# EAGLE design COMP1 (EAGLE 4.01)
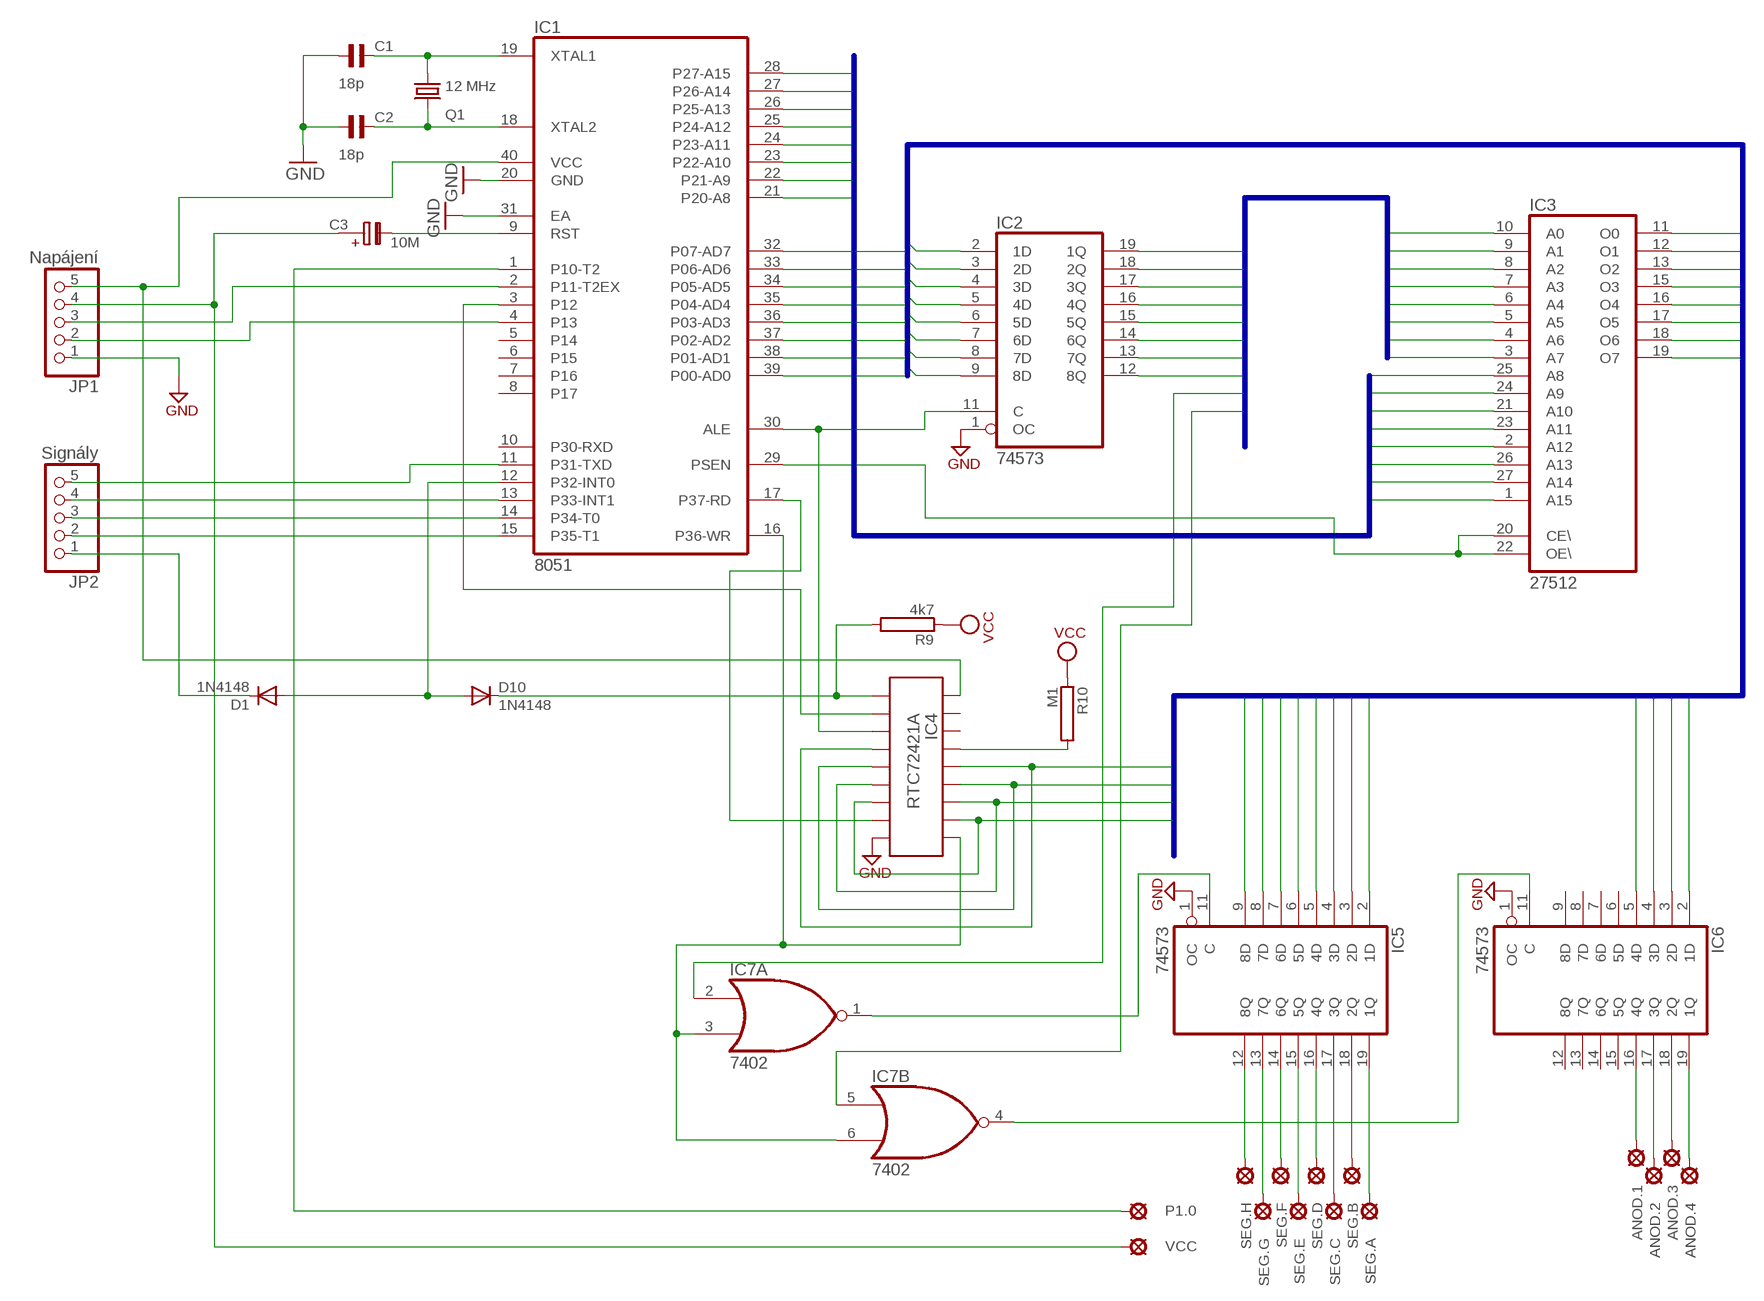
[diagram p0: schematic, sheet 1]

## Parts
ANOD.1  LSP10  [LSP10]
ANOD.2  LSP10  [LSP10]
ANOD.3  LSP10  [LSP10]
ANOD.4  LSP10  [LSP10]
C1  18p  C2,5  [C2,5-4]
C2  18p  C2,5  [C2,5-4]
C3  10M  TT2D4  [TT2D4]
D1  1N4148  [DO35-10]
D10  1N4148  [DO35-10]
IC1  8051  [DIL40]
IC2  74573  [DIL20]
IC3  27512  [DIL28]
IC4  RTC72421A  [DIL-18]
IC5  74573  [DIL20]
IC6  74573  [DIL20]
IC7  7402  [DIL14]
JP1  Napájení  PINHD-1X5  [1X05]
JP2  Signály  PINHD-1X5  [1X05]
P1.0  LSP10  [LSP10]
Q1  12 MHz  HC49U-V  [HC49U-V]
R9  4k7  0204/5  [0204/5]
R10  M1  0204/5  [0204/5]
SEG.A  LSP10  [LSP10]
SEG.B  LSP10  [LSP10]
SEG.C  LSP10  [LSP10]
SEG.D  LSP10  [LSP10]
SEG.E  LSP10  [LSP10]
SEG.F  LSP10  [LSP10]
SEG.G  LSP10  [LSP10]
SEG.H  LSP10  [LSP10]
VCC  LSP10  [LSP10]

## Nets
+5V/1: IC1.40(VCC) IC4.18 JP1.5
A0: IC2.19(1Q) IC3.10(A0)
A1: IC2.18(2Q) IC3.9(A1)
A2: IC2.17(3Q) IC3.8(A2)
A3: IC2.16(4Q) IC3.7(A3)
A4: IC2.15(5Q) IC3.6(A4) IC7.5(B:I0)
A5: IC2.14(6Q) IC3.5(A5) IC7.2(A:I0)
A6: IC2.13(7Q) IC3.4(A6)
A7: IC2.12(8Q) IC3.3(A7)
A8: IC1.21(P20-A8) IC3.25(A8)
A9: IC1.22(P21-A9) IC3.24(A9)
A10: IC1.23(P22-A10) IC3.21(A10)
A11: IC1.24(P23-A11) IC3.23(A11)
A12: IC1.25(P24-A12) IC3.2(A12)
A13: IC1.26(P25-A13) IC3.26(A13)
A14: IC1.27(P26-A14) IC3.27(A14)
A15: IC1.28(P27-A15) IC3.1(A15)
DB0: IC1.39(P00-AD0) IC2.2(1D) IC3.11(O0) IC4.4 IC4.14 IC5.2(1D) IC6.2(1D)
DB1: IC1.38(P01-AD1) IC2.3(2D) IC3.12(O1) IC4.5 IC4.13 IC5.3(2D) IC6.3(2D)
DB2: IC1.37(P02-AD2) IC2.4(3D) IC3.13(O2) IC4.6 IC4.12 IC5.4(3D) IC6.4(3D)
DB3: IC1.36(P03-AD3) IC2.5(4D) IC3.15(O3) IC4.7 IC4.11 IC5.5(4D) IC6.5(4D)
DB4: IC1.35(P04-AD4) IC2.6(5D) IC3.16(O4) IC5.6(5D)
DB5: IC1.34(P05-AD5) IC2.7(6D) IC3.17(O5) IC5.7(6D)
DB6: IC1.33(P06-AD6) IC2.8(7D) IC3.18(O6) IC5.8(7D)
DB7: IC1.32(P07-AD7) IC2.9(8D) IC3.19(O7) IC5.9(8D)
GND: C1.1 C2.1 IC1.20(GND) IC1.31(EA) IC2.1(OC) IC4.9 IC5.1(OC) IC6.1(OC) JP1.1
N$1: C2.2 IC1.18(XTAL2) Q1.2
N$2: C1.2 IC1.19(XTAL1) Q1.1
N$3: IC5.11(C) IC7.1(A:O)
N$4: IC6.11(C) IC7.4(B:O)
N$5: IC5.12(8Q) SEG.H.MP
N$6: IC5.13(7Q) SEG.G.MP
N$7: IC5.14(6Q) SEG.F.MP
N$8: IC5.15(5Q) SEG.E.MP
N$9: IC5.16(4Q) SEG.D.MP
N$10: IC1.11(P31-TXD) JP2.5
N$11: IC5.17(3Q) SEG.C.MP
N$13: IC5.18(2Q) SEG.B.MP
N$14: IC1.1(P10-T2) P1.0.MP
N$15: IC5.19(1Q) SEG.A.MP
N$16: ANOD.4.MP IC6.19(1Q)
N$17: D1.A D10.A IC1.12(P32-INT0)
N$18: ANOD.3.MP IC6.18(2Q)
N$19: ANOD.2.MP IC6.17(3Q)
N$21: IC1.14(P34-T0) JP2.3
N$22: ANOD.1.MP IC6.16(4Q)
N$23: C3.- IC1.9(RST)
N$24: IC1.2(P11-T2EX) JP1.3
N$25: IC1.4(P13) JP1.2
N$26: IC1.13(P33-INT1) JP2.4
N$27: IC1.30(ALE) IC2.11(C) IC4.3
N$28: IC1.29(PSEN) IC3.20(CE\) IC3.22(OE\)
N$29: D1.K JP2.1
N$32: IC1.15(P35-T1) JP2.2
N$33: D10.K IC4.1 R9.2
N$34: IC1.3(P12) IC4.2
N$35: IC4.15 R10.2
N$37: IC1.17(P37-RD) IC4.8
N$38: IC1.16(P36-WR) IC4.10 IC7.3(A:I1) IC7.6(B:I1)
VCC: C3.+ JP1.4 R9.1 R10.1 VCC.MP
Unconnected: IC1.5(P14) IC1.6(P15) IC1.7(P16) IC1.8(P17) IC1.10(P30-RXD) IC4.16 IC4.17 IC6.6(5D) IC6.7(6D) IC6.8(7D) IC6.9(8D) IC6.12(8Q) IC6.13(7Q) IC6.14(6Q) IC6.15(5Q) IC7.8(C:I0) IC7.9(C:I1) IC7.10(C:O) IC7.11(D:I0) IC7.12(D:I1) IC7.13(D:O)

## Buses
A[8..15]
DB[0..7]
A[0..7]

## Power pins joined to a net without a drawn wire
GND: IC2.10(GND) IC3.14(GND) IC5.10(GND) IC6.10(GND) IC7.7(P:GND)
VCC: IC2.20(VCC) IC3.28(VCC) IC5.20(VCC) IC6.20(VCC) IC7.14(P:VCC)

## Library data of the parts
ANOD.1-ANOD.4 P1.0 SEG.A SEG.B SEG.C SEG.D SEG.E SEG.F SEG.G SEG.H VCC = SOLPAD:LSP10
C1 C2 = cap:C2,5
C3 = CAP-TANT:TT2D4
D1 D10 = DIODE:1N4148
IC1 = INTEL:8051
IC2 IC5 IC6 = 74XX:74573
IC3 = MEMORY:27512
IC4 = GM397:RTC72421A
IC7 = 74XX:7402
JP1 JP2 = PINHEADb:PINHD-1X5
Q1 = QUARTZ:HC49U-V
R9 R10 = R:0204/5

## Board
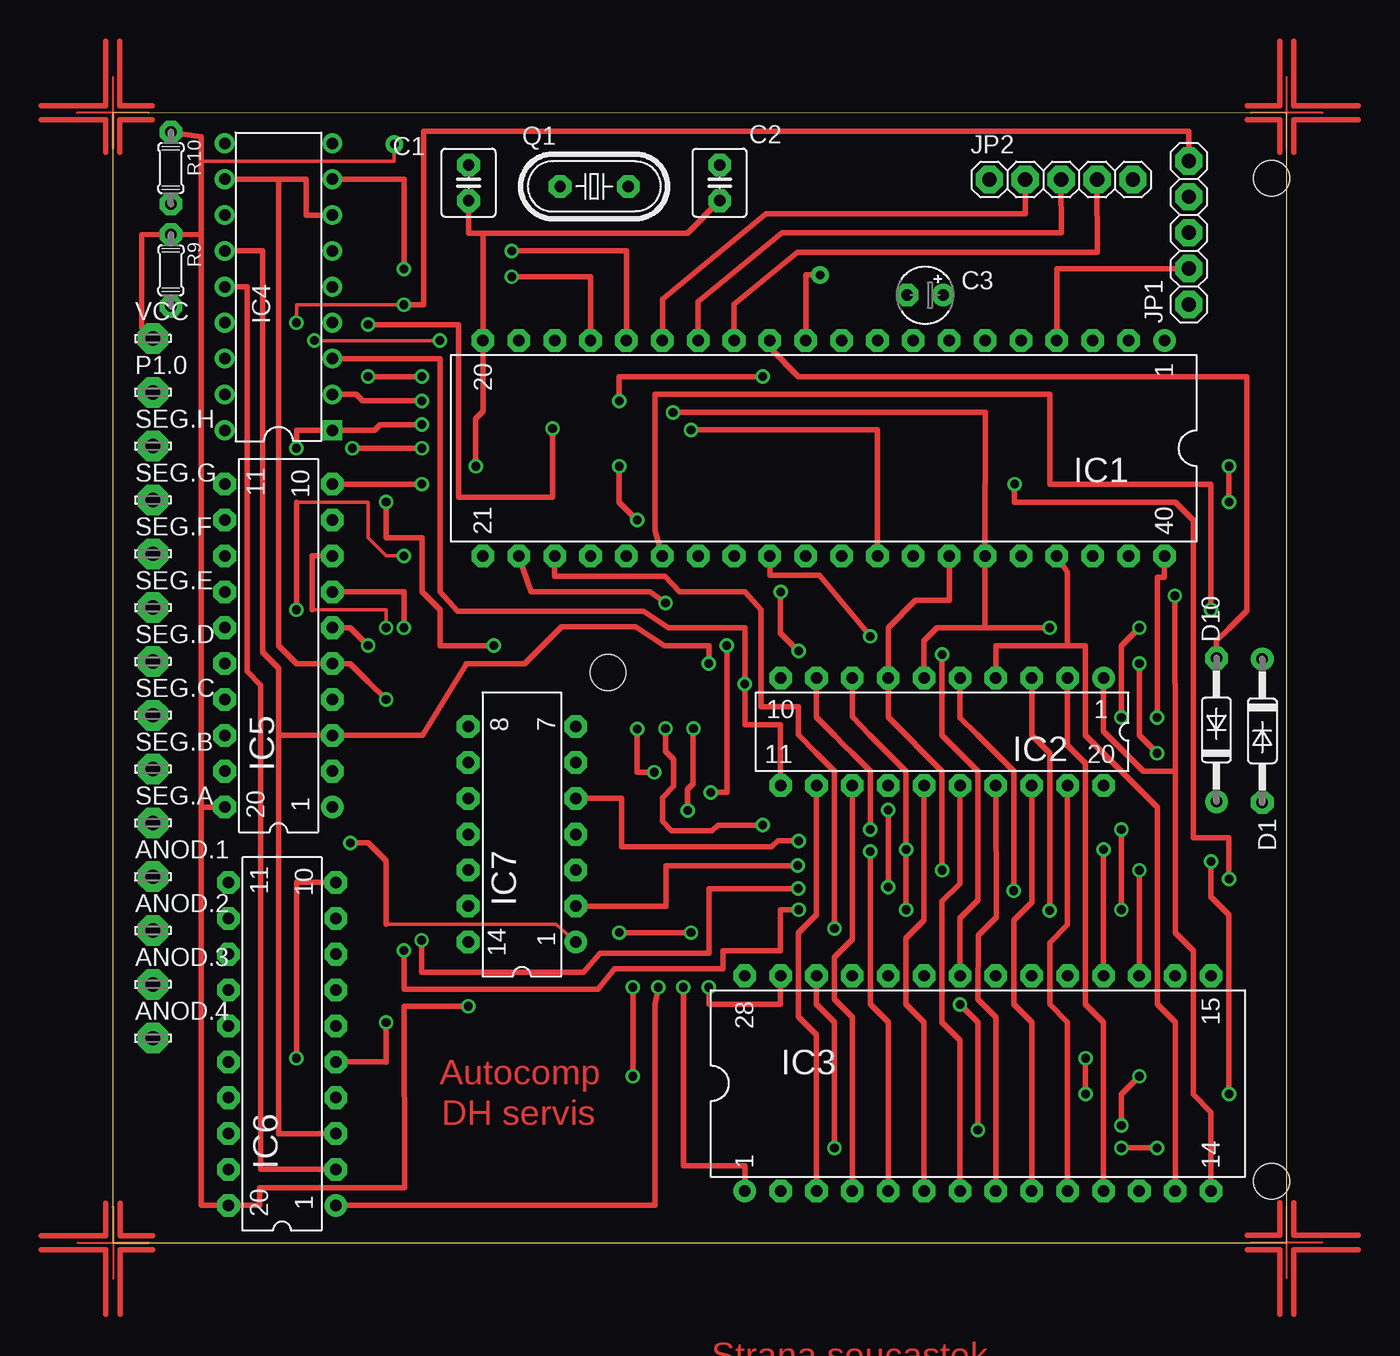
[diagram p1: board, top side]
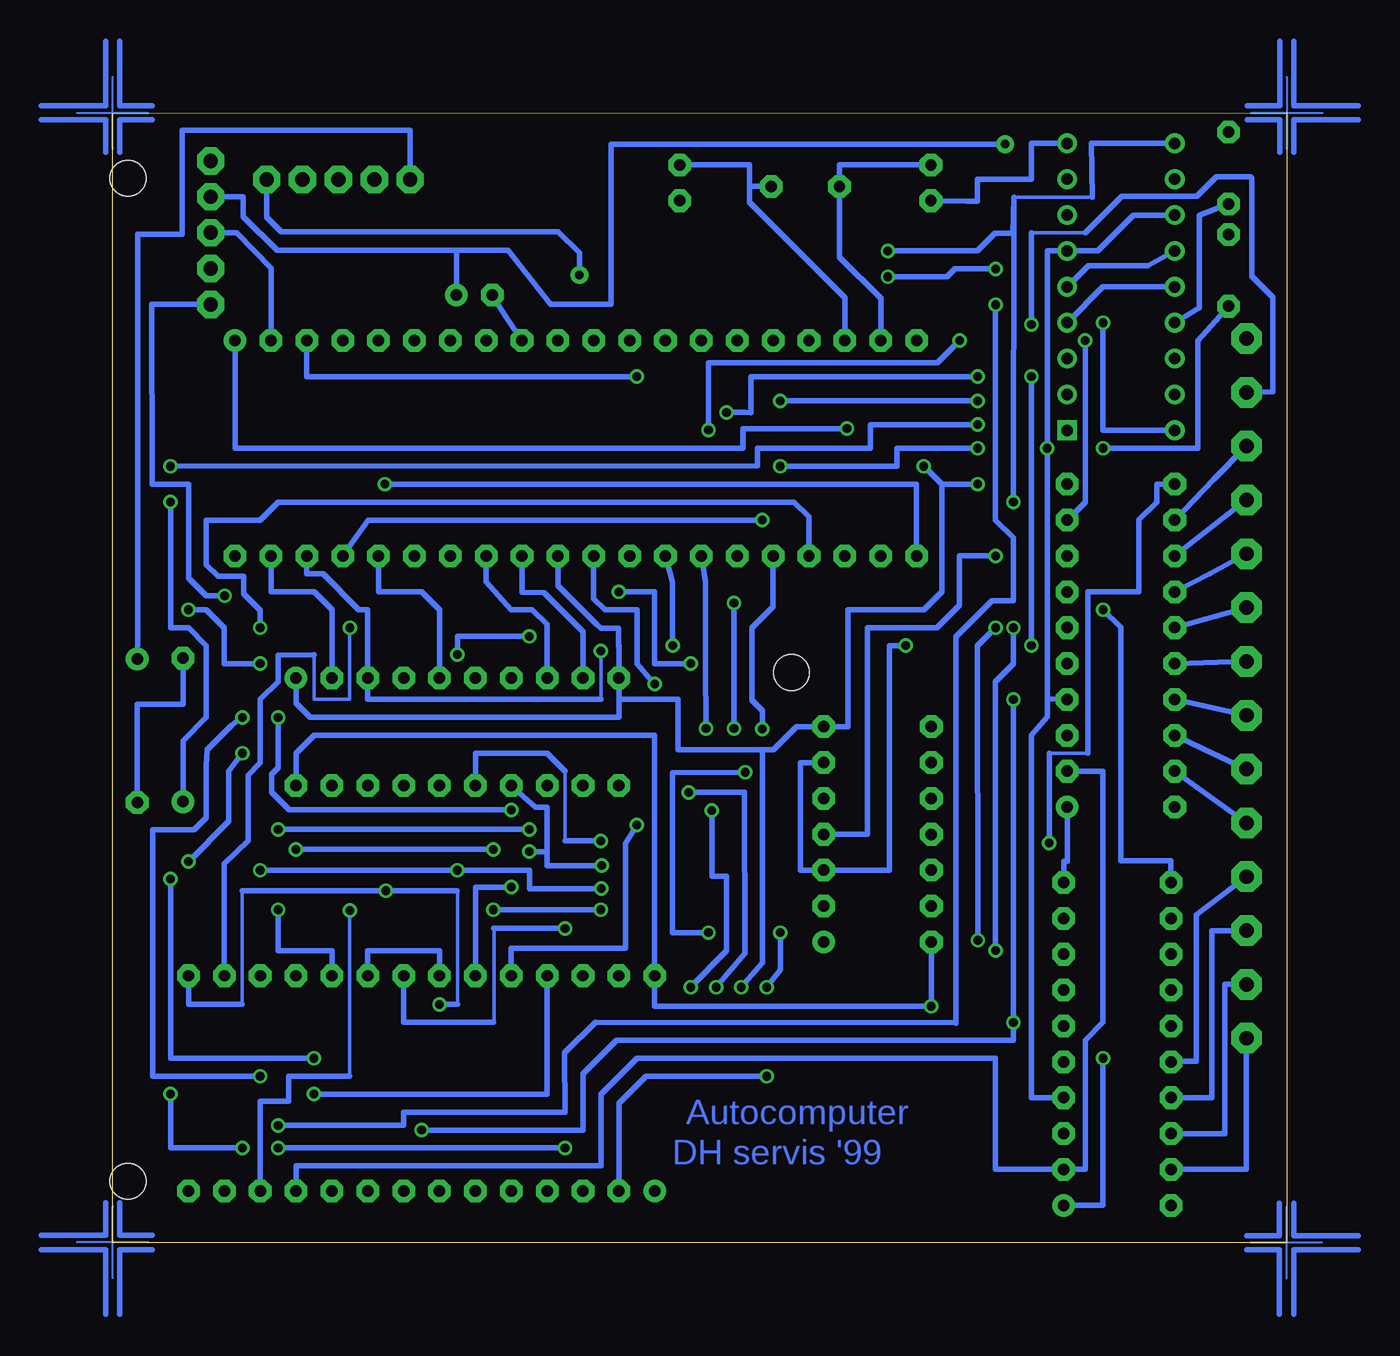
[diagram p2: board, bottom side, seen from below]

Size 83.13 x 80 mm. Coordinates in mm from the lower left corner, seen from the top.
Outline: 0,0.02 83.13,0 83.13,79.98 0,80 0,0.02
Copper layers used: Top, Bottom
Holes 2.54 mm at 35.05,40.38 82.05,4.38 82.05,75.38

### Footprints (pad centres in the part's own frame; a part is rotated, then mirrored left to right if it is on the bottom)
LSP10 = drill 1.016 pad 2.159 octagon: MP 0,0
C2,5-4 = drill 0.813 pad 1.6 octagon: 1 -1.27,0; 2 1.27,0
TT2D4 = drill 0.813 pad 1.6 round: + 1.27,0 | drill 0.813 pad 1.6 octagon: - -1.27,0
DO35-10 = drill 0.813 pad 1.6 octagon: A 5.08,0 | drill 0.813 pad 1.6 round: K -5.08,0
DIL40 = drill 0.813 pad 1.6 round: 1 -24.13,-7.62 | drill 0.813 pad 1.6 octagon: 2 -21.59,-7.62; 3 -19.05,-7.62; 4 -16.51,-7.62; 5 -13.97,-7.62; 6 -11.43,-7.62; 7 -8.89,-7.62; 8 -6.35,-7.62; 9 -3.81,-7.62; 10 -1.27,-7.62; 11 1.27,-7.62; 12 3.81,-7.62; 13 6.35,-7.62; 14 8.89,-7.62; 15 11.43,-7.62; 16 13.97,-7.62; 17 16.51,-7.62; 18 19.05,-7.62; 19 21.59,-7.62; 20 24.13,-7.62; 21 24.13,7.62; 22 21.59,7.62; 23 19.05,7.62; 24 16.51,7.62; 25 13.97,7.62; 26 11.43,7.62; 27 8.89,7.62; 28 6.35,7.62; 29 3.81,7.62; 30 1.27,7.62; 31 -1.27,7.62; 32 -3.81,7.62; 33 -6.35,7.62; 34 -8.89,7.62; 35 -11.43,7.62; 36 -13.97,7.62; 37 -16.51,7.62; 38 -19.05,7.62; 39 -21.59,7.62; 40 -24.13,7.62
DIL20 = drill 0.813 pad 1.6 round: 1 -11.43,-3.81 | drill 0.813 pad 1.6 octagon: 2 -8.89,-3.81; 3 -6.35,-3.81; 4 -3.81,-3.81; 5 -1.27,-3.81; 6 1.27,-3.81; 7 3.81,-3.81; 8 6.35,-3.81; 9 8.89,-3.81; 10 11.43,-3.81; 11 11.43,3.81; 12 8.89,3.81; 13 6.35,3.81; 14 3.81,3.81; 15 1.27,3.81; 16 -1.27,3.81; 17 -3.81,3.81; 18 -6.35,3.81; 19 -8.89,3.81; 20 -11.43,3.81
DIL28 = drill 0.813 pad 1.6 round: 1 -16.51,-7.62 | drill 0.813 pad 1.6 octagon: 2 -13.97,-7.62; 3 -11.43,-7.62; 4 -8.89,-7.62; 5 -6.35,-7.62; 6 -3.81,-7.62; 7 -1.27,-7.62; 8 1.27,-7.62; 9 3.81,-7.62; 10 6.35,-7.62; 11 8.89,-7.62; 12 11.43,-7.62; 13 13.97,-7.62; 14 16.51,-7.62; 15 16.51,7.62; 16 13.97,7.62; 17 11.43,7.62; 18 8.89,7.62; 19 6.35,7.62; 20 3.81,7.62; 21 1.27,7.62; 22 -1.27,7.62; 23 -3.81,7.62; 24 -6.35,7.62; 25 -8.89,7.62; 26 -11.43,7.62; 27 -13.97,7.62; 28 -16.51,7.62
DIL-18 = drill 0.813 pad 1.397 square: 1 -10.16,-3.81 | drill 0.813 pad 1.397 round: 2 -7.62,-3.81; 3 -5.08,-3.81; 4 -2.54,-3.81; 5 0,-3.81; 6 2.54,-3.81; 7 5.08,-3.81; 8 7.62,-3.81; 9 10.16,-3.81; 10 10.16,3.81; 11 7.62,3.81; 12 5.08,3.81; 13 2.54,3.81; 14 0,3.81; 15 -2.54,3.81; 16 -5.08,3.81; 17 -7.62,3.81; 18 -10.16,3.81
DIL14 = drill 0.813 pad 1.6 round: 1 -7.62,-3.81 | drill 0.813 pad 1.6 octagon: 2 -5.08,-3.81; 3 -2.54,-3.81; 4 0,-3.81; 5 2.54,-3.81; 6 5.08,-3.81; 7 7.62,-3.81; 8 7.62,3.81; 9 5.08,3.81; 10 2.54,3.81; 11 0,3.81; 12 -2.54,3.81; 13 -5.08,3.81; 14 -7.62,3.81
1X05 = drill 1.016 pad 1.93 octagon: 1 -5.08,0; 2 -2.54,0; 3 0,0; 4 2.54,0; 5 5.08,0
HC49U-V = drill 0.813 pad 1.6 octagon: 1 -2.413,0; 2 2.413,0
0204/5 = drill 0.813 pad 1.6 octagon: 1 -2.54,0; 2 2.54,0

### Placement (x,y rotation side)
ANOD.1  2.83,25.93 0 top
ANOD.2  2.83,22.12 0 top
ANOD.3  2.83,18.31 0 top
ANOD.4  2.83,14.5 0 top
C1  25.18,75.05 90 top
C2  42.96,75.05 90 top
C3  57.52,67.1 0 top
D1  81.39,36.25 270 top
D10  78.14,36.32 90 top
E$1  [ROH]  -0.01,80.01 270 top
E$2  [ROH]  0.01,0.02 0 top
E$3  [ROH]  83.12,80.01 180 top
E$4  [ROH]  83.12,0.05 90 top
IC1  50.33,56.26 180 top
IC2  58.71,36.19 180 top
IC3  61.25,11.3 0 top
IC4  11.72,67.69 90 top
IC5  11.72,42.29 90 top
IC6  11.98,14.09 90 top
IC7  28.96,28.93 90 top
JP1  76.19,71.52 90 top
JP2  67.14,75.28 0 top
P1.0  2.83,60.22 0 top
Q1  34.07,74.8 0 top
R9  4.1,68.85 270 top
R10  4.1,76.09 270 top
SEG.A  2.83,29.74 0 top
SEG.B  2.83,33.55 0 top
SEG.C  2.83,37.36 0 top
SEG.D  2.83,41.17 0 top
SEG.E  2.83,44.98 0 top
SEG.F  2.83,48.79 0 top
SEG.G  2.83,52.6 0 top
SEG.H  2.83,56.41 0 top
VCC  2.83,64.03 0 top

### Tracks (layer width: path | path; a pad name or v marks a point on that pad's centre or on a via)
+5V/1  (via drill 0.61 pad 1.02)
  Top 0.254: v12.99,65.15 12.99,66.42 v20.61,66.42
  Top 0.406: v20.61,66.42 21.98,66.42 21.98,78.68 76.19,78.68 JP1.5 | v73.95,37.21 73.95,47.11 74.46,47.11 IC1.40 | v72.68,11.81 71.41,10.54 v71.41,8.33
  Bottom 0.406: IC4.18 12.99,57.53 v12.99,65.15 | v72.68,11.81 80.3,11.81 80.3,29.26 77.36,29.26 76.49,30.12 76.49,33.75 76.44,34.92 74.71,36.65 v73.95,37.21 | v71.41,8.33 62.52,8.35 62.52,9.27 51.09,9.27 51.12,13.46 48.93,15.62 23.46,15.59 23.41,15.62 | v20.61,66.42 20.61,51.18 19.34,49.91 19.34,45.46 20.87,45.46 23.41,42.92 23.41,15.62 | 23.41,15.62 23.41,15.56
A0
  Top 0.406: IC3.10 67.6,15.62 66.33,16.89 66.33,21.05 66.33,21.26 67.6,22.53 IC2.19
A1
  Top 0.406: IC3.9 65.06,15.62 63.79,16.89 63.79,22.58 63.79,22.86 65.06,24.12 IC2.18
A2
  Top 0.406: IC3.8 62.52,15.97 61.25,17.24 61.3,21.79 62.57,23.06 IC2.17
A3
  Top 0.406: IC3.7 59.98,14.35 58.71,15.62 58.71,24.18 59.98,25.45 IC2.16
A4  (via drill 0.61 pad 1.02)
  Top 0.406: IC3.6 57.44,15.62 56.17,16.89 56.17,20.95 56.17,21.56 57.44,22.83 IC2.15 | IC7.5 36.03,31.47 36.03,28.04 46.65,28.04 47.08,28.47 v48.55,28.47
  Bottom 0.254: 51.09,33.4 51.09,28.47
  Bottom 0.406: 51.09,28.47 v48.55,28.47 | 51.09,33.4 52.36,34.67 57.44,34.67 IC2.15 57.44,32.13
A5  (via drill 0.61 pad 1.02)
  Top 0.406: v53.63,27.71 53.63,16.89 54.9,15.62 IC3.5 | v48.5,26.72 39.15,26.69 39.15,23.85 | IC7.2 39.15,23.85 | 39.15,23.85
  Bottom 0.406: 52.36,27.71 v53.63,27.71 | 52.36,27.71 52.36,30.86 53.17,30.86 IC2.14 | v48.5,26.72 52.36,26.72 52.36,27.71
A6
  Top 0.406: IC3.4 52.36,15.97 51.09,17.24 51.09,20.24 52.36,21.51 IC2.13
A7
  Top 0.406: IC3.3 49.82,14.75 48.55,16.02 48.55,21.97 49.82,23.24 IC2.12
A8  (via drill 0.61 pad 1.02)
  Top 0.406: v68.87,10.54 v68.87,13.08 | v79.03,25.78 79.03,28.67 76.49,28.67 76.49,51.18 75.22,52.45 63.84,52.45 v63.84,53.72
  Bottom 0.406: 53.76,10.54 v68.87,10.54 | v68.87,13.08 79.03,13.08 v79.03,25.78 | v63.84,53.72 26.2,53.72 IC1.21 | 53.76,10.54 53.63,10.54 | IC3.25 52.36,10.54 53.76,10.54
A9  (via drill 0.61 pad 1.02)
  Top 0.406: v39.13,45.31 38.04,46.1 29.6,46.1 IC1.22 | v39.13,36.42 39.13,34.82 39.71,34.23 39.71,32.33 38.9,31.52 38.9,29.84 39.56,29.18 42.43,29.18 42.84,29.59 v46.01,29.59
  Bottom 0.406: v39.13,36.42 v39.13,45.31 | v46.01,29.59 46.82,28.29 46.82,20.87 54.9,20.87 IC3.24
A10  (via drill 0.61 pad 1.02)
  Top 0.406: v51.09,22.27 51.09,33.4 49.8,34.72 48.55,35.99 48.55,37.94 45.88,37.94 45.88,44.83 44.74,46.1 40.12,46.1 39.1,47.21 31.28,47.21 IC1.23
  Bottom 0.254: 56.17,22.27 56.12,22.27 56.12,15.62 56.17,15.62
  Bottom 0.406: v51.09,22.27 56.17,22.27 | 62.52,16.94 IC3.21 | 62.52,16.94 62.52,16.89 | 56.17,15.62 62.52,15.62 62.52,16.94
A11  (via drill 0.61 pad 1.02)
  Top 0.406: v72.68,43.56 71.41,42.29 v71.41,37.21 | v54.9,25.19 v54.9,30.65
  Bottom 0.406: v54.9,25.19 57.44,25.19 IC3.23 | IC1.24 33.82,51.4 34.89,52.45 71.41,52.45 72.68,51.18 76.49,51.18 76.49,48.03 75.65,47.19 73.85,47.19 73.85,45.97 72.68,44.8 v72.68,43.56 | v54.9,30.65 70.62,30.65 71.87,31.9 71.87,33.17 71.41,33.62 71.41,35.66 | 71.41,35.66 v71.41,37.21 | 71.41,35.66 71.41,35.63
A12  (via drill 0.61 pad 1.02)
  Top 0.406: v36.82,11.81 v36.82,18.11 | v35.85,21.97 v40.93,21.97 | v37.12,36.39 37.12,33.32 v38.34,33.32
  Bottom 0.406: v36.82,11.81 45.35,11.81 47.28,9.88 IC3.2 | v40.93,21.97 43.47,21.97 43.47,33.29 v38.34,33.32 | v37.12,36.39 37.12,37.69 37.86,38.42 37.86,43.56 36.36,45.05 IC1.25 | v36.82,18.11 35.85,19.35 v35.85,21.97 35.85,21.99
A13  (via drill 0.61 pad 1.02)
  Top 0.406: v51.09,6.73 51.09,15.62 49.82,16.89 IC3.26 | v71.41,6.73 v73.95,6.73 | v79.03,10.54 79.03,23.24 77.76,24.51 v77.76,27 | v73.95,34.67 72.68,35.94 v72.68,41.02 | v77.76,44.83 77.76,53.72 66.33,53.72 66.33,60.07 65.04,60.07 | 65.04,60.07 38.39,60.07 38.39,50.41 IC1.26 | 65.04,60.07 65.06,60.07
  Bottom 0.406: v51.09,6.73 v71.41,6.73 | v73.95,6.73 79.03,6.73 v79.03,10.54 | v73.95,34.67 74.92,33.4 74.92,30.02 74.92,29.84 v77.76,27 | v72.68,41.02 75.22,41.02 75.22,43.56 76.49,44.83 v77.76,44.83
A14  (via drill 0.61 pad 1.02)
  Top 0.406: IC3.27 47.28,16.89 42.35,16.89 42.2,16.89 v42.2,18.11 | v40.7,30.63 40.7,32.13 41.08,32.51 41.08,36.42 v41.11,36.42
  Bottom 0.406: v41.11,36.42 41.14,41.02 41.14,46.76 IC1.27 | v42.2,18.11 39.66,20.7 39.66,25.95 40.7,25.95 v40.7,30.63
A15  (via drill 0.61 pad 1.02)
  Top 0.406: v40.4,18.11 40.4,5.46 44.74,5.46 IC3.1 | v42.33,31.9 43.47,31.9 v43.47,42.29
  Bottom 0.406: v40.4,18.11 38.37,20.49 38.39,31.9 v42.33,31.9 | v43.47,42.29 43.47,46.76 43.65,47.44 IC1.28
DB0
  Top 0.406: IC3.11 70.14,15.62 68.87,16.89 68.87,33.95 67.6,35.22 IC2.2 | IC4.14 9.49,67.69 9.49,40.46 10.45,39.49 10.45,5.2 IC6.2
  Bottom 0.406: 67.6,39.75 IC2.2 67.6,44.83 68.87,46.1 71.92,46.1 IC1.39 71.92,48.69 | IC4.14 13.02,67.69 IC4.4 | IC5.2 12.99,33.4 12.99,15.62 14.26,14.35 14.26,5.23 IC6.2 20.61,5.2 20.61,13.08 46.01,13.08 48.55,10.54 48.55,5.46 70.14,5.46 IC3.11
DB1  (via drill 0.61 pad 1.02)
  Top 0.406: v66.33,23.54 66.33,34.67 65.06,35.94 IC2.3 | 11.72,35.94 IC5.3 21.93,35.94 25.03,41.02 | 11.72,35.94 11.72,7.74 IC6.3 | IC4.13 10.6,70.23 10.6,41.8 11.72,40.69 11.72,35.94 | 25.03,41.02 29.15,41.02 | v42.2,41.02 42.2,42.29 39.05,42.26 37.02,43.63 31.76,43.63 29.15,41.02 | 25.03,41.02 25.01,41.02 | 29.15,41.02 29.12,40.99 | 29.15,41.02 29.17,41.02 | v48.55,41.9 47.28,43.17 v47.28,46.1
  Bottom 0.254: v66.33,23.54 66.33,11.81 | v48.55,41.9 48.55,38.48
  Bottom 0.406: 66.33,11.81 70.65,11.81 70.65,10.03 72.68,10.03 IC3.12 | IC4.5 14.03,69.19 9.82,69.19 | 9.82,69.19 10.86,69.19 | 48.55,38.48 65.06,38.48 IC2.3 65.06,44.83 65.7,44.83 68.24,47.37 69.38,47.37 IC1.38 69.38,48.66 | v47.28,46.1 44.74,46.1 44.74,41.02 v42.2,41.02 | IC4.13 9.82,69.19
DB2  (via drill 0.61 pad 1.02)
  Top 0.406: 67.6,42.29 62.52,42.29 IC2.4 62.52,39.75 | 67.6,42.29 67.6,47.47 IC1.37 | 67.6,42.29 68.87,42.29 68.87,35.94 73.95,30.86 73.95,30.48 73.95,16.89 75.22,15.62 IC3.13 | v37.12,51.18 35.85,52.45 v35.85,54.99 | v16.95,56.26 v21.88,56.26
  Bottom 0.406: 16.95,38.53 IC5.4 | IC6.4 18.07,10.28 18.07,35.94 16.95,37.26 16.95,38.53 | 16.95,38.53 v16.95,56.26 16.95,70.23 IC4.6 13.37,70.23 10.86,72.77 IC4.12 | v37.12,51.18 65.04,51.18 IC1.37 | v35.85,54.99 27.6,54.99 27.6,56.26 v21.88,56.26
DB3  (via drill 0.61 pad 1.02)
  Top 0.406: v63.79,24.94 63.79,33.4 61.2,35.99 59.98,37.18 IC2.5 | 11.72,75.31 13.68,75.31 13.68,72.77 IC4.7 | 11.72,75.31 IC4.11 | v19.34,38.48 18.07,39.75 16.8,40.99 IC5.5 12.99,41.02 11.72,42.29 11.72,75.31 | v59.98,16.89 61.25,15.62 v61.25,8 | 19.34,12.82 v19.34,15.62 | IC6.5 19.34,12.82 | 19.34,12.82 19.34,12.8
  Bottom 0.254: 58.74,24.94 58.71,24.94 58.71,16.89 | 73.95,24.94 73.95,16.89
  Bottom 0.406: 59.98,39.75 IC2.5 59.98,44.83 61.25,46.1 64.3,46.1 IC1.36 | 73.95,16.89 77.76,16.89 IC3.15 | 73.95,24.94 v63.79,24.94 58.74,24.94 | v19.34,38.48 v19.34,15.62 19.34,14.35 47.46,14.35 49.82,11.98 49.82,8 v61.25,8 | v59.98,16.89 58.71,16.89
DB4  (via drill 0.61 pad 1.02)
  Top 0.406: 61.76,43.56 59.3,43.56 | 61.76,43.56 IC1.35 61.79,58.8 v39.66,58.8 | 57.44,39.75 IC2.6 57.44,42.64 58.36,43.56 59.3,43.56 | 61.76,43.56 v66.33,43.56 | v18.07,61.34 v21.88,61.34 | IC5.6 16.8,43.56 v18.07,42.29 | 59.3,43.56 59.22,43.56
  Bottom 0.254: 68.87,41.63 68.87,38.48 66.33,38.48 v66.33,43.56
  Bottom 0.406: 73.55,32.05 73.55,28.47 75.25,26.84 IC3.16 | 68.87,41.63 71.41,41.6 71.41,39.75 72.68,38.48 72.68,33.98 73.55,33.12 73.55,32.05 | v21.88,61.34 37.93,61.34 37.93,58.77 38.39,58.8 v39.66,58.8 | v18.07,42.29 v18.07,61.34 | 73.55,32.05 73.55,32.07
DB5  (via drill 0.61 pad 1.02)
  Top 0.406: v20.61,43.56 20.61,46.1 IC5.7 | v58.71,26.39 58.71,33.4 54.9,37.21 IC2.7 54.9,43.56 56.83,45.49 59.22,45.49 IC1.34 | v72.68,26.39 IC3.17 | v48.53,25.09 42.2,25.09 42.2,20.49 34.48,20.49 33.31,19.17 21.86,19.17 v21.86,21.43
  Bottom 0.406: v72.68,26.39 v58.71,26.39 53.61,26.39 53.61,25.09 v48.53,25.09 | v20.61,43.56 21.88,42.29 v21.86,21.43
DB6  (via drill 0.61 pad 1.02)
  Top 0.254: v19.34,43.56 19.34,44.83 14.11,44.83
  Top 0.406: IC5.8 14.11,48.64 14.11,44.83 | v70.14,27.86 IC3.18 | IC2.8 52.36,37.26 53.58,35.99 56.17,33.4 v56.17,27.86 v56.17,23.59 | v48.55,23.59 47.28,23.59 47.28,20.7 43.19,20.7 43.19,19.43 35.52,19.43 34.35,17.95 20.61,17.95 v20.61,20.7
  Bottom 0.406: v56.17,27.86 v70.14,27.86 | 52.36,39.75 IC2.8 52.36,43.81 53.43,44.83 54.9,44.83 56.68,46.81 IC1.33 56.68,48.69 | v48.55,23.59 v56.17,23.59 | v19.34,43.56 19.34,41.02 20.61,39.75 v20.61,20.7
DB7  (via drill 0.61 pad 1.02)
  Top 0.254: v14.26,63.88 v23.15,63.88
  Top 0.406: v71.41,29.28 v71.41,23.59 | v53.63,29.28 53.63,33.4 52.36,34.67 51.75,35.25 51.09,35.94 49.82,37.21 IC2.9 | v40.93,57.55 54.14,57.55 IC1.32
  Bottom 0.406: 49.82,39.75 IC2.9 49.82,43.28 52.57,46.02 54.11,46.07 54.14,46.07 IC1.32 | v71.41,23.59 71.41,20.7 67.6,20.7 IC3.19 | v53.63,29.28 v71.41,29.28 | IC5.9 14.26,52.45 v14.26,63.88 | v23.15,63.88 24.73,62.3 40.93,62.3 v40.93,57.55
GND  (via drill 0.61 pad 1.02)
  Top 0.406: 75.22,33.4 72.96,33.4 70.14,36.21 70.14,36.62 | 75.22,33.4 75.22,21.97 76.49,20.7 76.49,10.54 77.76,9.27 IC3.14 | IC2.1 70.14,36.62 | 75.22,33.4 v75.2,45.82 | v12.99,13.08 12.99,25.5 13.02,25.52 IC6.10 | v21.88,53.72 IC5.10 | v38.62,18.11 38.39,16.89 38.39,2.66 IC6.1 | 70.14,36.62 70.14,36.49 | C2.1 40.68,71.5 25.59,71.5 | v25.69,54.99 25.69,58.36 26.2,58.87 IC1.20 26.2,71.5 25.59,71.5 | C1.1 25.18,71.5 25.59,71.5
  Bottom 0.406: v75.2,45.82 76.52,45.82 77.74,47.06 77.74,53.72 80.33,53.72 80.35,66.44 JP1.1 | IC4.9 18.07,77.85 18.07,75.31 21.88,75.31 21.88,73.76 22.64,73.76 C1.1 | v12.99,13.08 12.99,2.66 IC6.1 | 24.42,53.72 v21.88,53.72 | 24.42,53.72 24.4,46.1 25.67,44.83 31.05,44.83 31.05,36.55 IC7.7 34.7,36.55 35.9,35.35 | 47.28,38.48 IC2.10 47.28,42.29 47.31,42.29 47.31,43.53 48.55,43.53 48.83,43.76 51.6,46.53 IC1.31 | 24.42,53.72 v25.69,54.99 | 47.28,38.48 47.28,37.21 69.15,37.21 70.14,38.2 IC2.1 | IC5.1 15.53,27.02 15.79,27.02 IC6.10 15.79,25.5 | 47.28,38.48 43.09,38.48 43.09,34.92 37.12,34.92 | v38.62,18.11 37.12,19.83 37.12,34.92 | 35.9,35.35 35.93,35.33 | 37.12,34.92 36.33,34.92 35.9,35.35
N$1
  Bottom 0.406: 38.04,74.8 38.04,76.32 C2.2 | IC1.18 31.28,66.92 38.04,73.68 38.04,73.86 38.04,74.8 | 38.04,74.8 Q1.2 | 38.04,74.8 38.01,74.82
N$2
  Bottom 0.406: IC1.19 28.74,66.87 31.66,69.79 31.66,70.38 | Q1.1 31.66,74.77 | C1.2 31.66,76.32 Q1.1 | 31.66,70.38 Q1.1 | 31.66,70.38 31.66,70.15
N$3  (via drill 0.61 pad 1.02)
  Top 0.254: IC7.1 31.38,22.55 19.34,22.55
  Top 0.406: 19.34,22.55 19.34,27.05 18.07,28.32 v16.8,28.32
  Bottom 0.254: 16.8,34.67 14.08,34.67
  Bottom 0.406: v16.8,28.32 16.8,34.67 | 14.08,34.67 14.08,46.1 10.45,46.1 10.45,51.2 9.18,52.45 9.18,53.72 IC5.11
N$4  (via drill 0.61 pad 1.02)
  Top 0.254: v20.61,48.64 19.34,48.64 18.07,49.91 18.07,52.45 12.99,52.45
  Top 0.406: v12.99,44.83 12.99,52.45
  Bottom 0.406: v12.99,44.83 11.72,43.58 11.72,27.05 8.19,27.05 8.19,25.98 IC6.11 | v20.61,48.64 23.15,48.64 23.15,45.16 24.75,43.56 29.68,43.56 29.68,28.95 30.16,28.95 IC7.4
N$5
  Bottom 0.406: IC5.12 5.14,54.07 SEG.H.MP
N$6
  Bottom 0.406: SEG.G.MP IC5.13
N$7
  Bottom 0.406: IC5.14 5.42,47.37 SEG.F.MP
N$8
  Bottom 0.406: SEG.E.MP 5.8,44.14 IC5.15
N$9
  Bottom 0.406: SEG.D.MP IC5.16
N$10  (via drill 0.61 pad 1.27)
  Top 0.406: IC1.11 49.06,68.55 50.18,68.52 v50.08,68.52
  Bottom 0.406: JP2.5 72.22,72.61 71.21,71.6 51.57,71.6 50.08,70.1 v50.08,68.52
N$11
  Bottom 0.406: IC5.17 5.88,38.04 SEG.C.MP
N$13
  Bottom 0.406: SEG.B.MP 5.93,35 IC5.18
N$14  (via drill 0.61 pad 1.02)
  Top 0.406: v18.07,65.02 24.47,65.02 24.47,52.8 31.13,52.8 v31.13,57.65
  Bottom 0.254: 14.26,71.52 18.07,71.52
  Bottom 0.406: 18.07,71.52 v18.07,65.02 | v31.13,57.65 38.49,57.65 38.49,56.26 74.46,56.26 IC1.1 74.46,63.9 | P1.0.MP 0.98,60.24 0.98,66.95 2.48,68.45 2.48,75.38 2.58,75.48 4.97,75.48 6.34,74.11 11.67,74.11 14.26,71.52
N$15
  Bottom 0.406: IC5.19 5.96,31.97 SEG.A.MP
N$16
  Bottom 0.406: ANOD.4.MP 2.83,5.2 IC6.19
N$17
  Top 0.406: IC1.12 46.52,63.37 48.55,61.34 80.3,61.34 80.3,44.75 79.03,43.48 78.14,42.62 D10.A
  Bottom 0.406: D10.A 78.14,38.15 81.39,38.15 D1.A
N$18
  Bottom 0.406: ANOD.3.MP 4.38,18.31 4.38,7.74 IC6.18
N$19
  Bottom 0.406: ANOD.2.MP 5.3,22.12 5.3,10.28 IC6.17
N$21
  Top 0.406: IC1.14 41.44,66.62 47.38,71.52 67.17,71.52 JP2.3
N$22
  Bottom 0.406: ANOD.1.MP 6.39,23.24 6.39,12.85 7.25,12.85 IC6.16
N$23
  Bottom 0.406: IC1.9 55.23,65.5 C3.-
N$24
  Bottom 0.406: IC1.2 71.92,69.01 74.36,71.52 JP1.3
N$25
  Top 0.406: IC1.4 66.84,68.98 JP1.2
N$26
  Top 0.406: IC1.13 43.98,66.47 48.48,70.15 69.71,70.15 JP2.4
N$27  (via drill 0.61 pad 1.02)
  Top 0.406: IC4.3 23.15,62.61 23.18,46.1 24.42,44.72 37.58,44.72 39.33,43.56 44.74,43.56 v44.74,39.57 44.74,36.7 47.28,36.7 IC2.11 47.28,32.13
  Bottom 0.406: v44.74,39.57 46.01,41.02 46.01,44.83 48.27,44.83 49.06,45.59 IC1.30
N$28  (via drill 0.61 pad 1.02)
  Top 0.406: v58.71,41.65 58.71,35.94 61.25,33.4 61.25,24.25 59.98,22.98 IC3.22 | IC1.29 46.52,47.26 50.03,47.26 v53.63,42.95
  Bottom 0.406: IC3.22 59.98,20.7 65.06,20.7 IC3.20 | v53.63,42.95 58.71,42.95 v58.71,41.65
N$29
  Bottom 0.406: D1.K 81.37,43.03 81.37,71.39 78.22,71.39 78.22,78.79 62.06,78.79 JP2.1
N$32
  Top 0.406: JP2.2 64.6,72.87 46.24,72.87 38.9,66.8 IC1.15
N$33  (via drill 0.61 pad 1.02)
  Top 0.406: v79.03,54.99 v79.03,52.45 | v12.99,56.26 12.99,57.53 IC4.1 18.53,57.53 18.94,57.93 v21.88,57.93
  Bottom 0.406: v79.03,52.45 79.03,43.56 77.76,43.56 76.49,42.29 76.49,37.21 78.14,35.55 D10.K | v79.03,54.99 37.45,55.01 37.45,56.26 29.48,56.26 29.48,57.93 v21.88,57.93 | v12.99,56.26 6.29,56.26 6.29,63.88 R9.2
N$34  (via drill 0.61 pad 1.02)
  Top 0.406: v35.85,59.61 35.85,61.34 v46.01,61.34 | IC4.2 17.23,60.07 17.69,59.61 v21.88,59.61
  Bottom 0.406: v21.88,59.61 v35.85,59.61 | v46.01,61.34 69.38,61.34 IC1.3
N$35
  Bottom 0.406: IC4.15 6.16,66.21 6.18,72.77 R10.2
N$37  (via drill 0.61 pad 1.02)
  Top 0.406: IC4.8 20.61,75.31 v20.61,68.96 | v28.23,68.4 33.82,68.4 IC1.17
  Bottom 0.406: v28.23,68.4 24.04,68.4 23.48,68.96 v20.61,68.96 20.59,68.98
N$38  (via drill 0.61 pad 1.02)
  Top 0.406: v28.23,70.23 36.36,70.23 IC1.16 | v26.96,42.29 23.15,42.29 23.15,44.83 21.88,46.1 21.88,49.91 19.34,49.91 v19.34,52.45
  Bottom 0.254: 19.32,74.04 13.75,74.04
  Bottom 0.406: IC4.10 13.8,77.85 13.75,74.04 | v28.23,70.23 21.88,70.23 20.64,71.47 19.37,71.47 19.32,74.04 v19.34,52.45 | v26.96,42.29 28.1,42.29 28.1,26.39 IC7.3 34.43,26.39 34.43,34.01 IC7.6
VCC  (via drill 0.61 pad 1.02, 0.61 pad 1.27)
  Top 0.254: v19.93,77.8 19.93,76.58 6.24,76.58
  Top 0.406: 6.24,30.86 IC5.20 | 6.24,30.86 6.24,2.66 IC6.20 10.4,2.66 10.4,3.91 20.64,3.91 20.61,16.76 v25.16,16.76 | 6.24,30.86 6.26,71.37 | R10.1 6.26,78.3 6.24,76.58 6.26,71.37 | 2.04,67.53 2.04,71.37 R9.1 6.26,71.37 | 2.04,67.53 2.04,67.1 | VCC.MP 2.04,64.81 2.04,67.53
  Bottom 0.406: 70.14,32.13 IC2.20 70.14,34.67 68.87,35.94 44.74,35.94 IC3.28 44.74,16.76 v25.16,16.76 IC7.14 | 60.08,70.28 60.01,70.28 55.13,70.28 52.13,66.47 47.84,66.47 47.84,77.8 v19.93,77.8 | 60.08,70.28 71.49,70.28 73.88,72.66 73.88,74.06 JP1.4 | 60.08,70.28 58.79,70.28 C3.+

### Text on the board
Top: Autocomp | DH servis | Strana soucastek
Bottom: Autocomputer | DH servis '99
